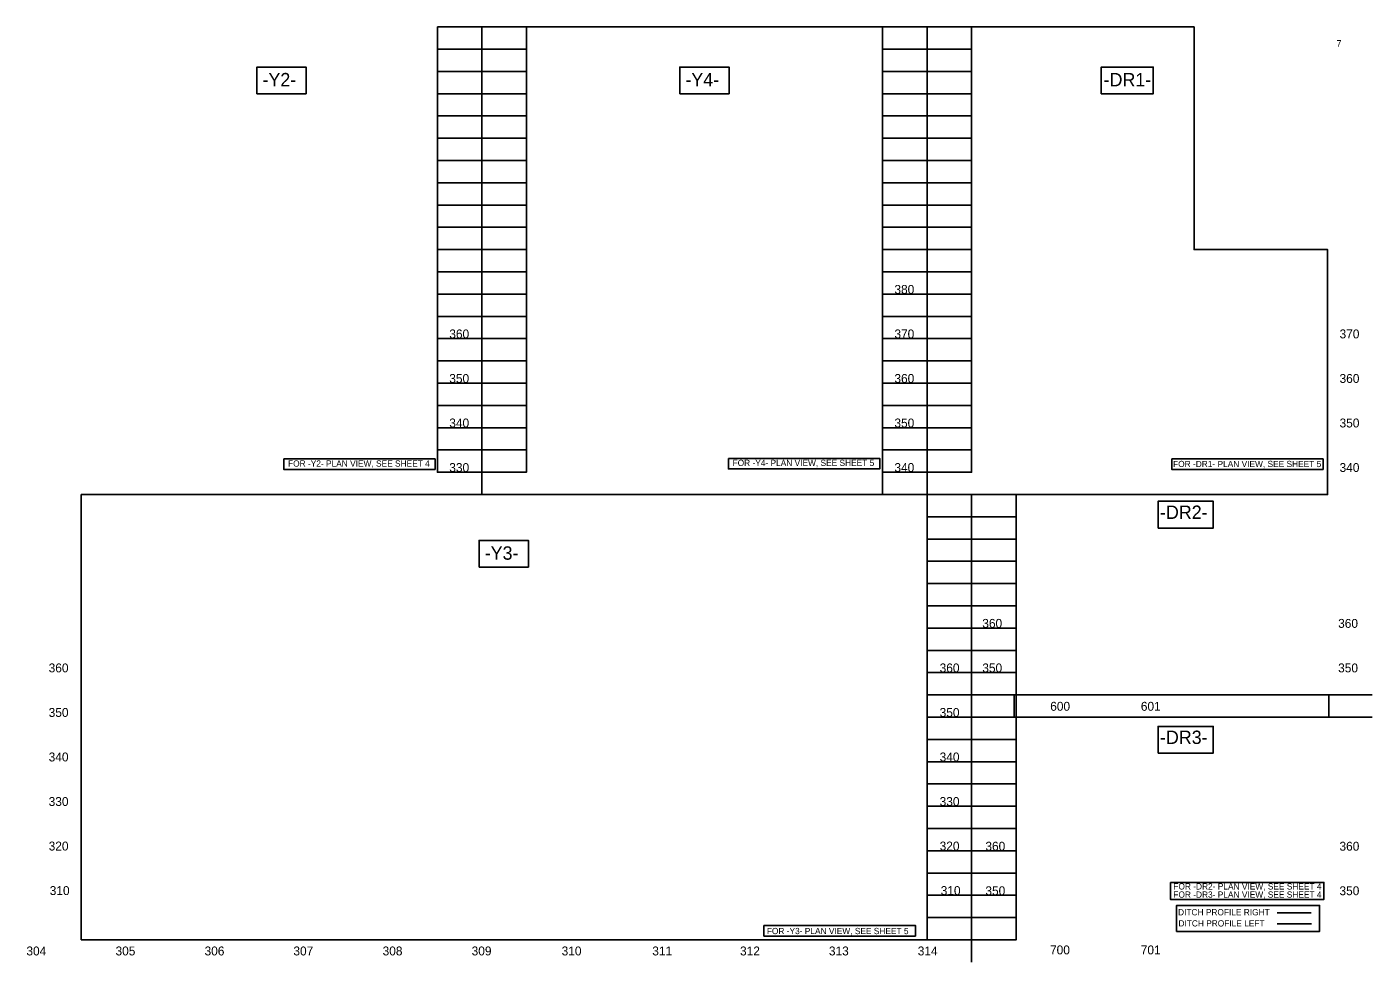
# Model space of a CAD drawing. Extents: x 2095738 to 2097249, y 866013 to 867063.
import ezdxf

# ---------------------------------------------------------------- set-up
doc = ezdxf.new("R2010")
doc.units = 0
for name, color, linetype in [('Exist Profile Cell', 7, 'Continuous'), ('Exist Vertical Profile Ground Line', 7, 'Continuous'), ('Exist Vertical Profile Horizontal Axis Label Major', 7, 'Continuous'), ('Exist Vertical Profile Vertical Axis Label', 7, 'Continuous'), ('Old_Level_1', 7, 'Continuous'), ('Prop Vertical Profile Curve Label', 7, 'Continuous'), ('Prop Vertical Profile Grade', 7, 'Continuous'), ('Prop Vertical Profile Grade Label', 7, 'Continuous'), ('Prop Vertical Profile Strip Grade', 7, 'Continuous'), ('Prop VPI Label', 7, 'Continuous'), ('Scratch_Level_0', 7, 'Continuous'), ('Scratch_Level_1', 7, 'Continuous'), ('Scratch_Level_4', 7, 'Continuous'), ('Scratch_Level_5', 7, 'Continuous')]:
    doc.layers.add(name, color=color, linetype=linetype)

msp = doc.modelspace()

# ---------------------------------------------------------------- linework, layer by layer
at = {"layer": 'Exist Profile Cell'}
for points in [[(2095996.8, 866988.3), (2096052.1, 866988.3), (2096052.1, 867018.3), (2095996.8, 867018.3)], [(2096471.8, 866988.3), (2096527.1, 866988.3), (2096527.1, 867018.3), (2096471.8, 867018.3)], [(2096945.3, 866988.3), (2097003.6, 866988.3), (2097003.6, 867018.3), (2096945.3, 867018.3)], [(2097009.1, 866500.7), (2097071, 866500.7), (2097071, 866530.7), (2097009.1, 866530.7)], [(2096246.4, 866456.8), (2096301.7, 866456.8), (2096301.7, 866486.8), (2096246.4, 866486.8)], [(2097009.1, 866248), (2097071, 866248), (2097071, 866278), (2097009.1, 866278)], [(2097029.8, 866047.8), (2097190.4, 866047.8), (2097190.4, 866077), (2097029.8, 866077)]]:
    msp.add_lwpolyline(points, close=True, dxfattribs=at)
at = {"layer": 'Exist Vertical Profile Ground Line'}
for p, q in [((2096249.5, 866538.3), (2096249.5, 867063.3)), ((2096749.5, 866538.3), (2096749.5, 867063.3)), ((2096799.5, 866013.3), (2096799.5, 866538.3)), ((2096799.5, 866313.3), (2097249.5, 866313.3)), ((2096799.5, 866288.3), (2097249.5, 866288.3))]:
    msp.add_line(p, q, dxfattribs=at)
at = {"layer": 'Exist Vertical Profile Horizontal Axis Label Major'}
for points in [[(2096199.5, 867063.3), (2096299.5, 867063.3), (2096299.5, 866563.3), (2096199.5, 866563.3)], [(2096699.5, 867063.3), (2096799.5, 867063.3), (2096799.5, 866563.3), (2096699.5, 866563.3)], [(2096749.5, 866538.3), (2096849.5, 866538.3), (2096849.5, 866038.3), (2096749.5, 866038.3)], [(2096847.4, 866313.3), (2097201, 866313.3), (2097201, 866288.3), (2096847.4, 866288.3)]]:
    msp.add_lwpolyline(points, close=True, dxfattribs=at)
at = {"layer": 'Exist Vertical Profile Vertical Axis Label'}
for p, q in [((2096199.5, 867013.3), (2096299.5, 867013.3)), ((2096699.5, 867013.3), (2096799.5, 867013.3)), ((2096199.5, 866963.3), (2096299.5, 866963.3)), ((2096699.5, 866963.3), (2096799.5, 866963.3)), ((2096199.5, 866913.3), (2096299.5, 866913.3)), ((2096699.5, 866913.3), (2096799.5, 866913.3)), ((2096199.5, 866863.3), (2096299.5, 866863.3)), ((2096699.5, 866863.3), (2096799.5, 866863.3)), ((2096199.5, 866813.3), (2096299.5, 866813.3)), ((2096699.5, 866813.3), (2096799.5, 866813.3)), ((2096199.5, 866763.3), (2096299.5, 866763.3)), ((2096699.5, 866763.3), (2096799.5, 866763.3)), ((2096199.5, 866713.3), (2096299.5, 866713.3)), ((2096699.5, 866713.3), (2096799.5, 866713.3)), ((2096199.5, 866663.3), (2096299.5, 866663.3)), ((2096699.5, 866663.3), (2096799.5, 866663.3)), ((2096199.5, 866613.3), (2096299.5, 866613.3)), ((2096699.5, 866613.3), (2096799.5, 866613.3)), ((2096749.5, 866488.3), (2096849.5, 866488.3)), ((2096749.5, 866438.3), (2096849.5, 866438.3)), ((2096749.5, 866388.3), (2096849.5, 866388.3)), ((2096749.5, 866338.3), (2096849.5, 866338.3)), ((2096749.5, 866288.3), (2096849.5, 866288.3)), ((2096749.5, 866238.3), (2096849.5, 866238.3)), ((2096749.5, 866188.3), (2096849.5, 866188.3)), ((2096749.5, 866138.3), (2096849.5, 866138.3)), ((2096749.5, 866088.3), (2096849.5, 866088.3))]:
    msp.add_line(p, q, dxfattribs=at)
at = {"layer": 'Old_Level_1'}
for points in [[(2096027, 866578.2), (2096197, 866578.2), (2096197, 866566.4), (2096027, 866566.4)], [(2096526.4, 866578.9), (2096696.5, 866578.9), (2096696.5, 866567.1), (2096526.4, 866567.1)], [(2097024.4, 866578.2), (2097194.4, 866578.2), (2097194.4, 866566.4), (2097024.4, 866566.4)], [(2097023, 866102.7), (2097195.3, 866102.7), (2097195.3, 866083.7), (2097023, 866083.7)], [(2096566.4, 866054.4), (2096736.4, 866054.4), (2096736.4, 866042.6), (2096566.4, 866042.6)]]:
    msp.add_lwpolyline(points, close=True, dxfattribs=at)
at = {"layer": 'Prop Vertical Profile Curve Label'}
for points in [[(2096249.5, 867063.3), (2096699.5, 867063.3), (2096699.5, 866538.3), (2096249.5, 866538.3)], [(2096749.5, 866538.3), (2097199.5, 866538.3), (2097199.5, 866813.3), (2097049.5, 866813.3), (2097049.5, 867063.3), (2096749.5, 867063.3)], [(2095799.5, 866038.3), (2096749.5, 866038.3), (2096749.5, 866538.3), (2095799.5, 866538.3)]]:
    msp.add_lwpolyline(points, close=True, dxfattribs=at)
at = {"layer": 'Scratch_Level_0'}
for p, q in [((2096199.5, 867038.3), (2096299.5, 867038.3)), ((2096699.5, 867038.3), (2096799.5, 867038.3)), ((2096199.5, 866988.3), (2096299.5, 866988.3)), ((2096699.5, 866988.3), (2096799.5, 866988.3)), ((2096199.5, 866938.3), (2096299.5, 866938.3)), ((2096699.5, 866938.3), (2096799.5, 866938.3)), ((2096199.5, 866888.3), (2096299.5, 866888.3)), ((2096699.5, 866888.3), (2096799.5, 866888.3)), ((2096199.5, 866838.3), (2096299.5, 866838.3)), ((2096699.5, 866838.3), (2096799.5, 866838.3)), ((2096199.5, 866788.3), (2096299.5, 866788.3)), ((2096699.5, 866788.3), (2096799.5, 866788.3)), ((2096199.5, 866738.3), (2096299.5, 866738.3)), ((2096699.5, 866738.3), (2096799.5, 866738.3)), ((2096199.5, 866688.3), (2096299.5, 866688.3)), ((2096699.5, 866688.3), (2096799.5, 866688.3)), ((2096199.5, 866638.3), (2096299.5, 866638.3)), ((2096699.5, 866638.3), (2096799.5, 866638.3)), ((2096199.5, 866588.3), (2096299.5, 866588.3)), ((2096699.5, 866588.3), (2096799.5, 866588.3)), ((2096749.5, 866513.3), (2096849.5, 866513.3)), ((2096749.5, 866463.3), (2096849.5, 866463.3)), ((2096749.5, 866413.3), (2096849.5, 866413.3)), ((2096749.5, 866363.3), (2096849.5, 866363.3)), ((2096749.5, 866313.3), (2096849.5, 866313.3)), ((2096749.5, 866263.3), (2096849.5, 866263.3)), ((2096749.5, 866213.3), (2096849.5, 866213.3)), ((2096749.5, 866163.3), (2096849.5, 866163.3)), ((2096749.5, 866113.3), (2096849.5, 866113.3)), ((2096749.5, 866063.3), (2096849.5, 866063.3))]:
    msp.add_line(p, q, dxfattribs=at)
at = {"layer": 'Scratch_Level_1'}
msp.add_line((2097143, 866068.5), (2097181.1, 866068.5), dxfattribs=at)
at = {"layer": 'Scratch_Level_5'}
msp.add_line((2097143, 866056.3), (2097181.3, 866056.3), dxfattribs=at)

# ---------------------------------------------------------------- texts
at = {"layer": 'Exist Profile Cell'}
for s, height, p in [('-Y2-', 15, (2096003.1, 866996.6)), ('-Y4-', 15, (2096478.1, 866996.6)), ('-DR1-', 15, (2096947.9, 866996.6)), ('380', 10, (2096712.9, 866763.6)), ('360', 10, (2096212.9, 866713.6)), ('370', 10, (2096712.9, 866713.6)), ('370', 10, (2097212.9, 866713.6)), ('350', 10, (2096212.9, 866663.6)), ('360', 10, (2096712.9, 866663.6)), ('360', 10, (2097212.9, 866663.6)), ('340', 10, (2096212.9, 866613.6)), ('350', 10, (2096712.9, 866613.6)), ('350', 10, (2097212.9, 866613.6)), ('330', 10, (2096212.9, 866563.6)), ('340', 10, (2096712.9, 866563.6)), ('340', 10, (2097212.9, 866563.6)), ('-DR2-', 15, (2097011.2, 866510.9)), ('-Y3-', 15, (2096252.7, 866465.1)), ('360', 10, (2096811.6, 866388.6)), ('360', 10, (2097211.3, 866388.6)), ('360', 10, (2095762.9, 866338.6)), ('360', 10, (2096763.7, 866338.6)), ('350', 10, (2096811.6, 866338.6)), ('350', 10, (2097211.3, 866338.6)), ('350', 10, (2095762.9, 866288.6)), ('350', 10, (2096763.7, 866288.6)), ('-DR3-', 15, (2097011.2, 866258.2)), ('340', 10, (2095762.9, 866238.6)), ('340', 10, (2096763.7, 866238.6)), ('330', 10, (2095762.9, 866188.6)), ('330', 10, (2096763.7, 866188.6)), ('320', 10, (2095762.9, 866138.6)), ('320', 10, (2096763.7, 866138.6)), ('360', 10, (2096815.1, 866138.4)), ('360', 10, (2097212.8, 866138.4)), ('310', 10, (2095764.1, 866088.6)), ('310', 10, (2096764.9, 866088.6)), ('350', 10, (2096815.1, 866088.4)), ('350', 10, (2097212.8, 866088.4))]:
    msp.add_text(s, height=height, dxfattribs=at).set_placement(p)
at = {"layer": 'Prop Vertical Profile Grade'}
msp.add_text('7', height=7.5, dxfattribs=at).set_placement((2097209.5, 867041))
at = {"layer": 'Prop Vertical Profile Grade Label'}
for s, p in [('600', (2096887.9, 866295.5)), ('601', (2096989.7, 866295.5)), ('304', (2095737.9, 866020.8)), ('305', (2095838, 866020.8)), ('306', (2095938, 866020.8)), ('307', (2096037.8, 866020.8)), ('308', (2096138, 866020.8)), ('309', (2096238, 866020.8)), ('310', (2096339.1, 866020.8)), ('311', (2096440.9, 866020.8)), ('312', (2096539.5, 866020.8)), ('313', (2096639.3, 866020.8)), ('314', (2096739.1, 866020.8)), ('700', (2096887.7, 866022)), ('701', (2096989.6, 866022))]:
    msp.add_text(s, height=10, dxfattribs=at).set_placement(p)
at = {"layer": 'Prop Vertical Profile Strip Grade'}
msp.add_text('DITCH PROFILE RIGHT', height=7, rotation=360, dxfattribs=at).set_placement((2097031.5, 866065.8))
at = {"layer": 'Prop VPI Label'}
for s, p in [('FOR -Y2- PLAN VIEW, SEE SHEET 4', (2096031.8, 866569.6)), ('FOR -Y4- PLAN VIEW, SEE SHEET 5', (2096531.1, 866570.3)), ('FOR -DR1- PLAN VIEW, SEE SHEET 5', (2097025.9, 866569.1)), ('FOR -DR2- PLAN VIEW, SEE SHEET 4', (2097026.2, 866094.8)), ('FOR -DR3- PLAN VIEW, SEE SHEET 4', (2097026.2, 866085.6)), ('FOR -Y3- PLAN VIEW, SEE SHEET 5', (2096569.6, 866044.7))]:
    msp.add_text(s, height=7, dxfattribs=at).set_placement(p)
at = {"layer": 'Scratch_Level_4'}
msp.add_text('DITCH PROFILE LEFT', height=7, rotation=360, dxfattribs=at).set_placement((2097031.9, 866053.3))

doc.saveas('drawing.dxf')
